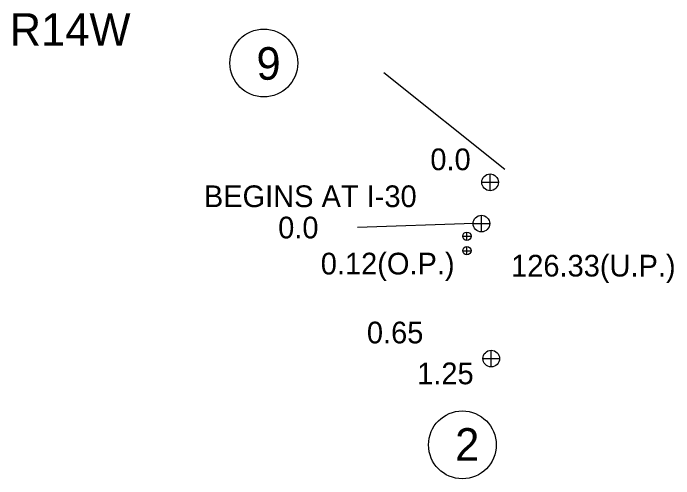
# Model space of a CAD drawing. Extents: x 1127717 to 1741049, y 2026793 to 2244711.
# Drawn here: x 1151686 to 1158117, y 2115370 to 2119899 of the extents above; entities that cross this region are included whole.
import ezdxf

# ---------------------------------------------------------------- set-up
doc = ezdxf.new("R2010")
doc.units = 0
for name, color, linetype in [('25', 7, 'Continuous'), ('26', 7, 'Continuous'), ('27', 7, 'Continuous'), ('30', 7, 'Continuous'), ('58', 7, 'Continuous')]:
    doc.layers.add(name, color=color, linetype=linetype)

msp = doc.modelspace()

# ---------------------------------------------------------------- linework, layer by layer
at = {"layer": '25'}
for p, q in [((1155292.4, 2119323.2), (1156472.5, 2118383.4)), ((1155038.4, 2117818.5), (1156168.9, 2117857.5))]:
    msp.add_line(p, q, dxfattribs=at)
at = {"layer": '26'}
for p, q in [((1156327.8, 2118172.8), (1156327.8, 2118335.3)), ((1156246.5, 2118254.1), (1156409, 2118254.1)), ((1156243.9, 2117771.3), (1156243.9, 2117933.8)), ((1156162.7, 2117852.5), (1156325.2, 2117852.5)), ((1156102.2, 2117688.7), (1156102.2, 2117769.9)), ((1156061.5, 2117729.3), (1156142.8, 2117729.3)), ((1156102.2, 2117548.3), (1156102.2, 2117629.6)), ((1156061.5, 2117589), (1156142.8, 2117589)), ((1156339.5, 2116457.5), (1156339.5, 2116620)), ((1156258.2, 2116538.8), (1156420.7, 2116538.8))]:
    msp.add_line(p, q, dxfattribs=at)
for centre, radius in [((1156327.8, 2118254.1), 81.2), ((1156243.9, 2117852.5), 81.2), ((1156102.2, 2117729.3), 40.6), ((1156102.2, 2117589), 40.6), ((1156339.5, 2116538.8), 81.2)]:
    msp.add_circle(centre, radius, dxfattribs=at)
at = {"layer": '27'}
for centre in [(1154125.8, 2119414.7), (1156059, 2115700)]:
    msp.add_circle(centre, 330, dxfattribs=at)

# ---------------------------------------------------------------- texts
at = {"layer": '25'}
for s, p in [('0.0', (1155746.9, 2118372.1)), ('BEGINS AT I-30', (1153542.1, 2118012.8)), ('0.0', (1154265.5, 2117708.7)), ('1.25', (1155618.7, 2116289.6))]:
    msp.add_text(s, height=211.2, dxfattribs=at).set_placement(p)
at = {"layer": '27'}
for s, p in [('9', (1154053.9, 2119252.3)), ('2', (1155988.1, 2115545.6))]:
    msp.add_text(s, height=316.8, dxfattribs=at).set_placement(p)
at = {"layer": '30'}
msp.add_text('R14W', height=316.8, dxfattribs=at).set_placement((1151651.3, 2119582.6))
at = {"layer": '58'}
for s, p in [('0.12(O.P.)', (1154680, 2117357.8)), ('126.33(U.P.)', (1156532.9, 2117337.6)), ('0.65', (1155129.2, 2116687.3))]:
    msp.add_text(s, height=211.2, dxfattribs=at).set_placement(p)

doc.saveas('drawing.dxf')
